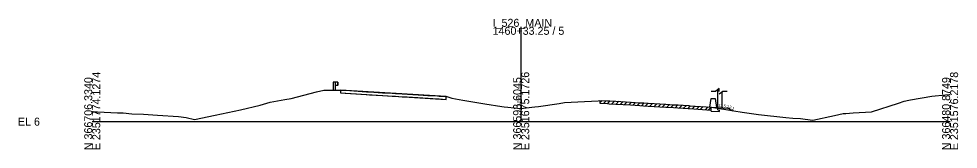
# Model space of a CAD drawing. Extents: x -170 to 2527928, y -10 to 1619750.
# Drawn here: x 5974.3 to 6302.8, y 5990.3 to 6036.1 of the extents above; entities that cross this region are included whole.
import ezdxf

# ---------------------------------------------------------------- set-up
doc = ezdxf.new("R2010")
doc.units = 0
for name, color, linetype in [('Default', 7, 'Continuous'), ('RD_GPK_XS_Cell', 7, 'Continuous'), ('RD_PD_NOISE-WALL-GM', 7, 'Continuous'), ('RD_XS_Base', 7, 'Continuous'), ('RD_XS_EarthShd', 7, 'Continuous'), ('RD_XS_ExGround', 7, 'Continuous'), ('RD_XS_ExPaveRet', 7, 'Continuous'), ('RD_XS_GR', 7, 'Continuous'), ('RD_XS_PaveShd', 7, 'Continuous'), ('RD_XS_TX_Elev_EX', 7, 'Continuous'), ('RD_XS_TX_Slope', 7, 'Continuous')]:
    doc.layers.add(name, color=color, linetype=linetype)

msp = doc.modelspace()

# ---------------------------------------------------------------- linework, layer by layer
at = {"layer": 'Default'}
for p, q in [((6217.98, 6010.63), (6216.4, 6010.63)), ((6219.23, 6011.66), (6217.98, 6010.63)), ((6219.23, 6010.63), (6219.23, 6011.66)), ((6220.48, 6010.63), (6219.23, 6009.61)), ((6222.08, 6010.63), (6220.48, 6010.63))]:
    msp.add_line(p, q, dxfattribs=at)
at = {"layer": 'RD_GPK_XS_Cell'}
for p, q in [((6150, 6000), (6150, 6033.27)), ((6000, 6000), (6150, 6000)), ((6150, 6000), (6300, 6000))]:
    msp.add_line(p, q, dxfattribs=at)
at = {"layer": 'RD_PD_NOISE-WALL-GM'}
for p, q in [((6218.82, 6004.97), (6218.82, 6011.3)), ((6220.32, 6004.9), (6220.32, 6010.48)), ((6216, 6005.1), (6216.48, 6008.1)), ((6216.48, 6008.1), (6217.82, 6008.1)), ((6217.82, 6008.1), (6218.32, 6004.99))]:
    msp.add_line(p, q, dxfattribs=at)
at = {"layer": 'RD_XS_Base'}
for p, q in [((6216.45, 6003.71), (6216.45, 6005.07)), ((6216.45, 6003.71), (6219.32, 6003.57)), ((6218.82, 6004.1), (6218.82, 6004.97)), ((6218.82, 6004.1), (6219.32, 6004.07)), ((6219.32, 6003.57), (6219.32, 6004.07))]:
    msp.add_line(p, q, dxfattribs=at)
at = {"layer": 'RD_XS_EarthShd'}
for p, q in [((6218.82, 6004.97), (6222.32, 6004.69)), ((6222.32, 6004.69), (6224.02, 6003.84))]:
    msp.add_line(p, q, dxfattribs=at)
at = {"layer": 'RD_XS_ExGround'}
msp.add_lwpolyline([(6000, 6003.43), (6001.81, 6003.42), (6008.81, 6003.13), (6010.8, 6003.13), (6013.84, 6002.71), (6017.88, 6002.66), (6022.85, 6002.3), (6030.16, 6001.86), (6032.87, 6001.45), (6035.77, 6000.79), (6042.93, 6002.22), (6051.81, 6004.11), (6058.76, 6005.79), (6062.2, 6006.85), (6067.36, 6007.77), (6069.52, 6008.1), (6078.38, 6010.41), (6081.01, 6011.09), (6086.12, 6011.09), (6087.04, 6011.08), (6088.53, 6010.99), (6095.85, 6010.5), (6096.99, 6010.42), (6101.54, 6010.16), (6104.91, 6009.97), (6106.07, 6009.9), (6108.4, 6009.76), (6110.2, 6009.65), (6113.95, 6009.44), (6117.37, 6009.23), (6117.48, 6009.23), (6120.77, 6009.03), (6121.34, 6008.98), (6123.99, 6008.8), (6124.67, 6008.62), (6125.76, 6008.2), (6129.64, 6007.55), (6137.26, 6006.27), (6143.21, 6005.27), (6144.11, 6005.16), (6145.32, 6005.07), (6149.72, 6004.66), (6154.81, 6005.18), (6156.05, 6005.28), (6163.34, 6006.39), (6165.19, 6006.66), (6169.84, 6006.95), (6176.92, 6007.3), (6177.49, 6007.45), (6180.22, 6007.32), (6180.84, 6007.3), (6183.11, 6007.16), (6188.24, 6006.85), (6191.51, 6006.64), (6192.79, 6006.56), (6194.46, 6006.45), (6200.62, 6006.08), (6203.37, 6005.93), (6204.88, 6005.84), (6208.45, 6005.64), (6208.61, 6005.63), (6208.99, 6005.6), (6216.56, 6005.06), (6224.32, 6003.79), (6227.29, 6003.32), (6228.95, 6003.06), (6232.99, 6002.52), (6242.59, 6001.48), (6244.96, 6001.27), (6247.74, 6001.06), (6249.28, 6000.83), (6251.97, 6000.52), (6259.62, 6002.19), (6262.62, 6002.83), (6263.59, 6002.88), (6266.05, 6003.07), (6272.52, 6003.45), (6281.9, 6006.47), (6283.98, 6007.14), (6285.6, 6007.51), (6286.12, 6007.61), (6293.57, 6008.99), (6298.36, 6009.45), (6299.83, 6009.57), (6300, 6009.56)], dxfattribs=at)
at = {"layer": 'RD_XS_ExPaveRet'}
for p, q in [((6086.83, 6011.09), (6086.83, 6010.1)), ((6123.82, 6007.81), (6123.82, 6008.81)), ((6177.49, 6007.45), (6177.49, 6006.45)), ((6177.49, 6006.62), (6178.27, 6007.41)), ((6178.78, 6006.39), (6179.71, 6007.32)), ((6180.24, 6006.32), (6181.18, 6007.27)), ((6181.72, 6006.24), (6182.68, 6007.2)), ((6183.11, 6006.06), (6184.18, 6007.14)), ((6184.67, 6006.06), (6185.62, 6007.01)), ((6186.15, 6005.98), (6187.1, 6006.92)), ((6187.63, 6005.89), (6188.57, 6006.83)), ((6189.1, 6005.79), (6190.04, 6006.74)), ((6190.57, 6005.7), (6191.51, 6006.64)), ((6192.05, 6005.6), (6192.99, 6006.55)), ((6193.52, 6005.51), (6194.46, 6006.45)), ((6194.99, 6005.42), (6195.93, 6006.36)), ((6196.46, 6005.33), (6197.41, 6006.28)), ((6197.94, 6005.24), (6198.88, 6006.19)), ((6199.41, 6005.15), (6200.36, 6006.1)), ((6200.89, 6005.07), (6201.84, 6006.01)), ((6202.37, 6004.98), (6203.31, 6005.93)), ((6203.84, 6004.9), (6204.79, 6005.84)), ((6205.33, 6004.81), (6206.28, 6005.76)), ((6206.82, 6004.73), (6207.77, 6005.67)), ((6208.31, 6004.64), (6209.25, 6005.58)), ((6209.78, 6004.54), (6210.72, 6005.48)), ((6211.26, 6004.43), (6212.19, 6005.37)), ((6212.73, 6004.33), (6213.66, 6005.27)), ((6214.5, 6004.21), (6215.43, 6005.14)), ((6215.52, 6004.12), (6216.45, 6005.05)), ((6216.45, 6004.07), (6216.45, 6005.07))]:
    msp.add_line(p, q, dxfattribs=at)
msp.add_lwpolyline([(6086.83, 6011.09), (6086.83, 6010.1), (6123.82, 6007.81), (6123.82, 6008.81)], close=True, dxfattribs=at)
for points in [[(6086.83, 6010.09), (6087.01, 6010.08), (6088.47, 6009.99), (6095.78, 6009.5), (6096.92, 6009.43), (6101.49, 6009.16), (6104.85, 6008.97), (6106.01, 6008.9), (6108.34, 6008.76), (6110.14, 6008.65), (6113.89, 6008.44), (6117.31, 6008.24), (6117.42, 6008.23), (6120.7, 6008.03), (6121.27, 6007.99), (6123.82, 6007.81)], [(6177.49, 6006.45), (6180.18, 6006.32), (6180.79, 6006.3), (6183.05, 6006.16), (6188.18, 6005.86), (6191.44, 6005.64), (6192.73, 6005.56), (6194.4, 6005.45), (6200.56, 6005.09), (6203.31, 6004.93), (6204.82, 6004.84), (6208.39, 6004.64), (6208.54, 6004.63), (6208.92, 6004.6), (6216.45, 6004.07)]]:
    msp.add_lwpolyline(points, dxfattribs=at)
at = {"layer": 'RD_XS_GR'}
for p, q in [((6084.92, 6013.85), (6084.25, 6013.85)), ((6084.25, 6013.85), (6084.25, 6011.09)), ((6085.83, 6013.85), (6084.92, 6013.85)), ((6084.92, 6013.85), (6084.92, 6011.09)), ((6085.83, 6012.68), (6084.92, 6012.68)), ((6085.83, 6012.68), (6085.83, 6013.85)), ((6085.83, 6013.78), (6086, 6013.58)), ((6086, 6013.53), (6085.83, 6013.33)), ((6086, 6013.01), (6085.83, 6013.21)), ((6085.83, 6012.76), (6086, 6012.96)), ((6086, 6013.58), (6086, 6013.53)), ((6086, 6012.96), (6086, 6013.01))]:
    msp.add_line(p, q, dxfattribs=at)
at = {"layer": 'RD_XS_PaveShd'}
msp.add_line((6216.45, 6005.08), (6218.82, 6004.97), dxfattribs=at)

# ---------------------------------------------------------------- texts
at = {"layer": 'RD_GPK_XS_Cell'}
for s, p in [('I_526_MAIN', (6140, 6033.27)), ('1460+33.25 / 5', (6140, 6030.47)), ('EL 6', (5974, 5998.6))]:
    msp.add_text(s, height=2.8, dxfattribs=at).set_placement(p)
for s, p in [('N 366706.3340', (6000, 5990)), ('E 2351774.1274', (6002.8, 5990)), ('N 366593.6045', (6150, 5990)), ('E 2351675.1726', (6152.8, 5990)), ('E 2351576.2178', (6302.8, 5990)), ('N 366480.8749', (6300, 5990))]:
    msp.add_text(s, height=2.8, rotation=90, dxfattribs=at).set_placement(p)
at = {"layer": 'RD_XS_TX_Elev_EX'}
msp.add_text('10.69', height=1, rotation=90, dxfattribs=at).set_placement((6149.5, 6005.69))
at = {"layer": 'RD_XS_TX_Slope'}
for s, rotation, p in [('12.5:1', 355.4261, (6218.85, 6005.17)), ('2:1', 333.4349, (6222.55, 6004.82))]:
    msp.add_text(s, height=1, rotation=rotation, dxfattribs=at).set_placement(p)

doc.saveas('drawing.dxf')
